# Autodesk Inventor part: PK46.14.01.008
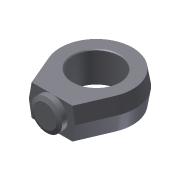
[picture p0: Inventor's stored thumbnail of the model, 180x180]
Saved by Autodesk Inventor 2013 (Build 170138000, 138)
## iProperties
Shininess: 64.0
Angle Display Precision: 2
Document Length Units: 11269
Document Angle Units: 11279
Document Time Units: 11290
Document Mass Units: 11283
Document Length Units Precision: 3
Document Angle Units Precision: 2
Created: 2003-06
Part Number: PK46.14.01.008
Material: Steel, Mild
Description: Проушина
Document SubType Name: Modeling
Designer: Ситников
Density: 1 g/cm^3
Density: 0.0
Volumn: 0.0
Area: 0.0
PropertySet Name: Model Information
Control State: 0
Master: False
Checked Out: True
Checked Out Date: 2008-10-15
Last Check In Date: 2008-10-15
Title: Проушина
Author: Ситников
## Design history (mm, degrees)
sketch "Sketch5"
  geometry: C1 r 22.5 at (0, 0) reference
sketch "Sketch6"
  geometry: C1 r 19.918 at (0, 0) reference
sketch "Sketch2"
  geometry: L1 (39.569, -30)-(-39.569, -30) reference; L2 (-70, 30)-(70, 30) reference; L3 (0, 30)-(0, -30); L4 (-45, 0)-(45, 0); C1 r 30 at (0, 0); 2 further points
  constraints: 4 end point, 3 midpoint, 1 centre point, 1 perpendicular
  dimensions: "d10" = 60 diameter of C1
sketch "Sketch3"
  geometry: A1 r 70 centre (0, 0) between (64.447, -27.324) and (-64.447, -27.324) reference
sketch "Sketch4" dims "d24" = 105
  geometry: L1 (39.569, -86)-(0, -86) reference; L2 (0, 0)-(0, 52.5); C1 r 46.6 at (0, 0) reference
  constraints: 2 end point, 1 coincident, 1 perpendicular, 1 vertical alignment, 2 other
body "Solid1"
sketch "Sketch1"
  geometry: L1 (-69.05, -29.276)-(-45, -86); L2 (-45, -86)-(45, -86); L3 (45, -86)-(69.05, -29.276); A1 r 75 centre (0, 0) between (69.05, -29.276) and (-69.05, -29.276)
  constraints: 6 end point, 2 point on circle, 2 tangent, 1 centre point, 1 horizontal, 1 other
  dimensions: "d0" = 150 diameter of A1; "d1" = 86 distance from line of A1.centre L2; "d2" = 90 distance of L1.end L2.end; "d3" = 45 horizontal distance of A1.centre L1.end
extrude "Extrusion1" new body sketch "Sketch1" stored distance "d4" = 60; taper "d5" = 0 deg
chamfer "Chamfer1" distance "d6" = 5; stored, may be unused: second distance "d7" = 30, angle "d51" = 45 deg
chamfer "Chamfer2" distance "d8" = 5; stored, may be unused: second distance "d9" = 30, angle "d52" = 45 deg
extrude "Extrusion2" join sketch "Sketch2" distance "d11" = 14; taper "d12" = 0 deg
chamfer "Chamfer3" distance "d13" = 7.5; stored, may be unused: angle "d14" = 25 deg, second distance "d53" = 7.5
hole "Hole1" sketch "Sketch3" diameter "d15" = 90; stored, may be unused: countersink angle "d19" = 82 deg, drill point angle "d21" = 118 deg; dims "d16" = 6, "d17" = 4, "d18" = 2, "d20" = 8
chamfer "Chamfer4" distance "d22" = 1.6; stored, may be unused: second distance "d23" = 1.6, angle "d54" = 45 deg
hole "Hole2" sketch "Sketch4" diameter "d25" = 6.647; stored, may be unused: countersink angle "d29" = 82 deg, drill point angle "d31" = 118 deg; dims "d26" = 18, "d27" = 11.2, "d28" = 2, "d30" = 23
pattern_circular "Circular Pattern1" dims angle "d34" = 360 deg
mirror "Mirror1"
hole "Hole3" sketch "Sketch5" diameter "d35" = 39.835; stored, may be unused: countersink angle "d39" = 82 deg, drill point angle "d41" = 0 deg; dims "d36" = 31.5, "d37" = 11.2, "d38" = 2, "d40" = 31.5
hole "Hole4" sketch "Sketch6" diameter "d42" = 43; stored, may be unused: countersink angle "d46" = 82 deg, drill point angle "d48" = 0 deg; dims "d43" = 31.5, "d44" = 11.2, "d45" = 2, "d47" = 8.5
chamfer "Chamfer5" distance "d49" = 0.5; stored, may be unused: second distance "d50" = 0.5, angle "d55" = 45 deg
